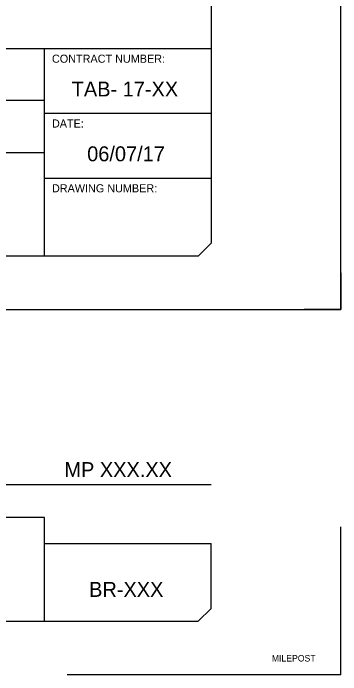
# Model space of a CAD drawing. Extents: x -0.04 to 1.42, y -0.15 to 0.92.
# Drawn here: x 1.285 to 1.4167, y -0.1467 to 0.1191 of the extents above; entities that cross this region are included whole.
import ezdxf

# ---------------------------------------------------------------- set-up
doc = ezdxf.new("R2010")
doc.units = 0
for name, color, linetype in [('SHEET_BORDER', 7, 'Continuous'), ('SHEET_BORDER_EDGE', 7, 'Continuous'), ('SHEET_BORDER_TEXT', 7, 'Continuous'), ('SHEET_BORDER_TEXT_SHEETINFO', 7, 'Continuous')]:
    doc.layers.add(name, color=color, linetype=linetype)

# ---------------------------------------------------------------- blocks, each defined once
blk = doc.blocks.new('twy_border_sheet')
at = {"layer": 'SHEET_BORDER_EDGE'}
blk.add_lwpolyline([(0, -0.300743), (0.464785, -0.300743), (0.464785, 0), (0, 0)], close=True, dxfattribs=at)
blk = doc.blocks.new('NSB_SI')
at = {"layer": 'SHEET_BORDER_EDGE'}
blk.add_blockref('twy_border_sheet', (0, 0), dxfattribs=at)

msp = doc.modelspace()

# ---------------------------------------------------------------- linework, layer by layer
at = {"layer": 'SHEET_BORDER'}
for p, q in [((1.36458, 0.10482), (0.66497, 0.10482)), ((1.29753, 0.02148), (1.29753, 0.10482)), ((1.29753, 0.08398), (1.14779, 0.08398)), ((1.36458, 0.07878), (1.29753, 0.07878)), ((0.91471, 0.06315), (1.29753, 0.06315)), ((1.36458, 0.05273), (1.29753, 0.05273))]:
    msp.add_line(p, q, dxfattribs=at)
msp.add_lwpolyline([(1.36458, 0.02669), (1.35937, 0.02148), (0.05729, 0.02148), (0.05208, 0.02669), (0.05208, 0.88997), (0.05729, 0.89518), (1.35937, 0.89518), (1.36458, 0.88997)], close=True, dxfattribs=at)
at = {"layer": 'SHEET_BORDER_EDGE'}
msp.add_lwpolyline([(1.41667, 0.01473), (1.41667, 0), (1.40194, 0)], dxfattribs=at)
at = {"layer": 'SHEET_BORDER_TEXT_SHEETINFO'}
for p, q in [((1.14779, -0.07024), (1.36458, -0.07024)), ((1.29753, -0.0836), (1.14779, -0.0836)), ((1.29753, -0.12526), (1.29753, -0.0836)), ((1.41667, -0.14675), (1.41667, -0.08725)), ((1.29753, -0.09401), (1.36458, -0.09401)), ((1.36458, -0.12005), (1.36458, -0.09401)), ((1.35937, -0.12526), (1.36458, -0.12005)), ((1.14779, -0.12526), (1.35937, -0.12526)), ((1.41667, -0.14675), (1.30661, -0.14675))]:
    msp.add_line(p, q, dxfattribs=at)

# ---------------------------------------------------------------- block references
at = {"layer": 'SHEET_BORDER', "xscale": 3.0480060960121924, "yscale": 3.0480060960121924}
msp.add_blockref('NSB_SI', (0, 0.91667), dxfattribs=at)

# ---------------------------------------------------------------- texts
at = {"layer": 'SHEET_BORDER'}
for s, height, p in [('CONTRACT NUMBER:', 0.0032552, (1.30053, 0.09921)), ('DATE:', 0.003255, (1.30053, 0.07316)), ('DRAWING NUMBER:', 0.0032552, (1.30053, 0.04712))]:
    msp.add_text(s, height=height, dxfattribs=at).set_placement(p)
at = {"layer": 'SHEET_BORDER_TEXT'}
for s, p in [('MP XXX.XX', (1.30553, -0.0673)), ('BR-XXX', (1.31547, -0.11544))]:
    msp.add_text(s, height=0.006, dxfattribs=at).set_placement(p)
at = {"layer": 'SHEET_BORDER_TEXT_SHEETINFO'}
for s, height, p in [('TAB- 17-XX', 0.006, (1.30847, 0.08565)), ('06/07/17', 0.006, (1.3147, 0.05961)), ('MILEPOST', 0.002605, (1.38893, -0.14142))]:
    msp.add_text(s, height=height, dxfattribs=at).set_placement(p)

doc.saveas('drawing.dxf')
